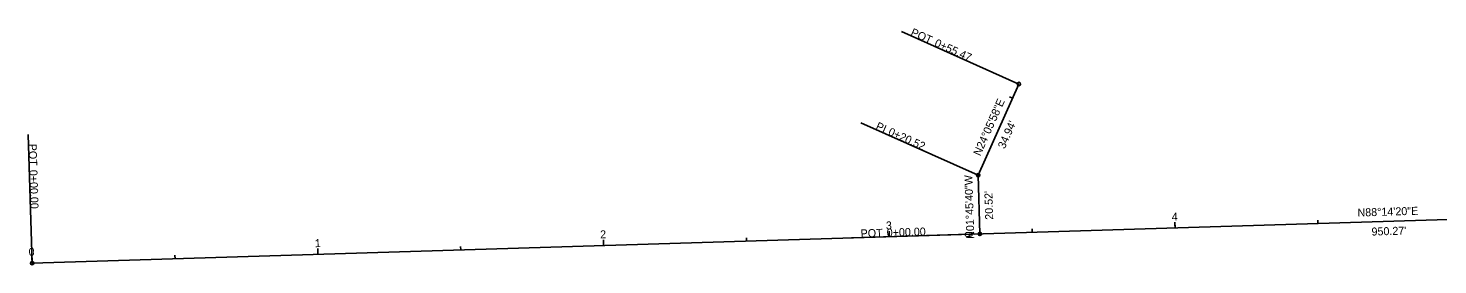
# Model space of a CAD drawing. Extents: x 2189302 to 2190256, y 657273 to 657356.
# Drawn here: x 2189302.4 to 2189795.5, y 657273 to 657355.8 of the extents above; entities that cross this region are included whole.
import ezdxf

# ---------------------------------------------------------------- set-up
doc = ezdxf.new("R2010")
doc.units = 0
for name, color, linetype in [('_CIVIL_CONSTRUCTION', 7, 'Continuous'), ('BR_P_Gen_Approach_Slab', 7, 'Continuous'), ('BR_P_Rail_Object', 7, 'Continuous'), ('BR_X_SV_Deck_Floor', 7, 'Continuous'), ('UT_X_Electric', 7, 'Continuous'), ('UT_X_Gas', 7, 'Continuous'), ('UT_X_Water', 7, 'Continuous')]:
    doc.layers.add(name, color=color, linetype=linetype)

msp = doc.modelspace()

# ---------------------------------------------------------------- linework, layer by layer
at = {"layer": '_CIVIL_CONSTRUCTION'}
for p, q in [((2189634.74, 657304.35), (2189649.01, 657336.25)), ((2189634.74, 657304.35), (2189635.37, 657283.84)), ((2189635.37, 657283.84), (2189634.74, 657304.35)), ((2189303.83, 657273.65), (2190253.65, 657302.85))]:
    msp.add_line(p, q, dxfattribs=at)
at = {"layer": 'BR_P_Rail_Object'}
for p, q in [((2189649.01, 657336.25), (2189607.93, 657354.62)), ((2189646.77, 657331.26), (2189645.68, 657331.75)), ((2189634.74, 657304.35), (2189593.66, 657322.73)), ((2189303.83, 657273.65), (2189302.44, 657318.63)), ((2189603.68, 657282.87), (2189603.62, 657284.86)), ((2189653.66, 657284.4), (2189653.62, 657285.6)), ((2189703.64, 657285.94), (2189703.58, 657287.94)), ((2189753.61, 657287.47), (2189753.58, 657288.67)), ((2189503.73, 657279.79), (2189503.67, 657281.79)), ((2189553.71, 657281.33), (2189553.67, 657282.53)), ((2189635.37, 657283.84), (2189590.39, 657282.46)), ((2189635.37, 657283.84), (2189633.37, 657283.78)), ((2189303.83, 657273.65), (2189303.76, 657275.65)), ((2189353.8, 657275.18), (2189353.76, 657276.38)), ((2189403.78, 657276.72), (2189403.72, 657278.72)), ((2189453.75, 657278.26), (2189453.72, 657279.46))]:
    msp.add_line(p, q, dxfattribs=at)
for centre in [(2189649.01, 657336.25), (2189634.74, 657304.35), (2189635.37, 657283.84), (2189303.83, 657273.65)]:
    msp.add_circle(centre, 0.6, dxfattribs=at)
at = {"layer": 'BR_X_SV_Deck_Floor'}
for p, q in [((2189649.01, 657336.25), (2189607.93, 657354.62)), ((2189634.74, 657304.35), (2189593.66, 657322.73)), ((2189303.83, 657273.65), (2189302.44, 657318.63)), ((2189635.37, 657283.84), (2189590.39, 657282.46)), ((2189635.37, 657283.84), (2189633.37, 657283.78)), ((2189303.83, 657273.65), (2189303.76, 657275.65))]:
    msp.add_line(p, q, dxfattribs=at)
for centre in [(2189649.01, 657336.25), (2189634.74, 657304.35), (2189635.37, 657283.84), (2189303.83, 657273.65)]:
    msp.add_circle(centre, 0.6, dxfattribs=at)
at = {"layer": 'UT_X_Electric'}
for p, q in [((2189649.01, 657336.25), (2189607.93, 657354.62)), ((2189634.74, 657304.35), (2189593.66, 657322.73)), ((2189303.83, 657273.65), (2189302.44, 657318.63)), ((2189703.64, 657285.94), (2189703.6, 657287.14)), ((2189503.73, 657279.79), (2189503.69, 657280.99)), ((2189635.37, 657283.84), (2189590.39, 657282.46)), ((2189603.68, 657282.87), (2189603.65, 657284.06)), ((2189635.37, 657283.84), (2189633.37, 657283.78)), ((2189303.83, 657273.65), (2189303.76, 657275.65)), ((2189403.78, 657276.72), (2189403.74, 657277.92))]:
    msp.add_line(p, q, dxfattribs=at)
for centre in [(2189649.01, 657336.25), (2189634.74, 657304.35), (2189635.37, 657283.84), (2189303.83, 657273.65)]:
    msp.add_circle(centre, 0.6, dxfattribs=at)

# ---------------------------------------------------------------- texts
at = {"layer": 'BR_P_Gen_Approach_Slab'}
for s, rotation, p in [('N24°05\'58"E', 65.9005, (2189635.48, 657310.91)), ("34.94'", 65.9005, (2189644.05, 657313.41)), ('N01°45\'40"W', 91.761, (2189633.42, 657282.18)), ("20.52'", 91.761, (2189640.02, 657288.85)), ('N88°14\'20"E', 1.761, (2189767.5, 657289.9)), ("950.27'", 1.761, (2189772.4, 657283.25))]:
    msp.add_text(s, height=2.8, rotation=rotation, dxfattribs=at).set_placement(p)
at = {"layer": 'BR_P_Rail_Object'}
for s, rotation, p in [('POT', 335.9005, (2189610.9, 657353.35)), ('0+55.47', 335.9005, (2189619.24, 657349.62)), ('PI', 335.9005, (2189598.68, 657320.54)), ('0+20.52', 335.9005, (2189603.04, 657318.58)), ('POT', 271.761, (2189302.59, 657315.33)), ('0+00.00', 271.761, (2189302.87, 657306.21)), ('4', 1.761, (2189702.5, 657288.4)), ('2', 1.761, (2189502.56, 657282.26)), ('POT', 1.761, (2189593.68, 657282.6)), ('3', 1.761, (2189602.52, 657285.38)), ('0+00.00', 1.761, (2189602.81, 657282.89)), ('0', 91.761, (2189632.86, 657282.66)), ('1', 1.761, (2189402.76, 657279.19)), ('0', 1.761, (2189302.64, 657276.16))]:
    msp.add_text(s, height=2.8, rotation=rotation, dxfattribs=at).set_placement(p)
at = {"layer": 'BR_X_SV_Deck_Floor'}
for s, rotation, p in [('POT', 335.9005, (2189610.9, 657353.35)), ('0+55.47', 335.9005, (2189619.24, 657349.62)), ('PI', 335.9005, (2189598.68, 657320.54)), ('0+20.52', 335.9005, (2189603.04, 657318.58)), ('POT', 271.761, (2189302.59, 657315.33)), ('0+00.00', 271.761, (2189302.87, 657306.21)), ('POT', 1.761, (2189593.68, 657282.6)), ('0+00.00', 1.761, (2189602.81, 657282.89)), ('0', 91.761, (2189632.86, 657282.66)), ('0', 1.761, (2189302.64, 657276.16))]:
    msp.add_text(s, height=2.8, rotation=rotation, dxfattribs=at).set_placement(p)
at = {"layer": 'UT_X_Electric'}
for s, rotation, p in [('POT', 335.9005, (2189610.9, 657353.35)), ('0+55.47', 335.9005, (2189619.24, 657349.62)), ('PI', 335.9005, (2189598.68, 657320.54)), ('0+20.52', 335.9005, (2189603.04, 657318.58)), ('POT', 271.761, (2189302.59, 657315.33)), ('0+00.00', 271.761, (2189302.87, 657306.21)), ('POT', 1.761, (2189593.68, 657282.6)), ('0+00.00', 1.761, (2189602.81, 657282.89)), ('0', 91.761, (2189632.86, 657282.66)), ('0', 1.761, (2189302.64, 657276.16))]:
    msp.add_text(s, height=2.8, rotation=rotation, dxfattribs=at).set_placement(p)
at = {"layer": 'UT_X_Gas'}
for s, rotation, p in [('N24°05\'58"E', 65.9005, (2189635.48, 657310.91)), ("34.94'", 65.9005, (2189644.05, 657313.41)), ('N01°45\'40"W', 91.761, (2189633.42, 657282.18)), ("20.52'", 91.761, (2189640.02, 657288.85)), ('N88°14\'20"E', 1.761, (2189767.5, 657289.9)), ("950.27'", 1.761, (2189772.4, 657283.25))]:
    msp.add_text(s, height=2.8, rotation=rotation, dxfattribs=at).set_placement(p)
at = {"layer": 'UT_X_Water'}
for s, rotation, p in [('N24°05\'58"E', 65.9005, (2189635.48, 657310.91)), ("34.94'", 65.9005, (2189644.05, 657313.41)), ('N01°45\'40"W', 91.761, (2189633.42, 657282.18)), ("20.52'", 91.761, (2189640.02, 657288.85)), ('N88°14\'20"E', 1.761, (2189767.5, 657289.9)), ("950.27'", 1.761, (2189772.4, 657283.25))]:
    msp.add_text(s, height=2.8, rotation=rotation, dxfattribs=at).set_placement(p)

doc.saveas('drawing.dxf')
